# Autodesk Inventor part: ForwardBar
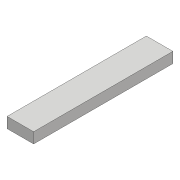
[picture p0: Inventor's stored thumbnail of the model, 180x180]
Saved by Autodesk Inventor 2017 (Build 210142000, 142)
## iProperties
Part Number: ForwardBar
Material: 一般
Document SubType Name: Modeling
Designer: kyushu-hep
Density: 1 g/cm^3
Appearance: 既定
Author: kyushu-hep
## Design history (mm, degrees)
sketch "スケッチ1"
  geometry: L1 (40.301, 16.049)-(-64.699, 16.049); L2 (-64.699, 16.049)-(-64.699, 8.049); L3 (-64.699, 8.049)-(40.301, 8.049); L4 (40.301, 8.049)-(40.301, 16.049); 2 further points
  constraints: 8 end point, 2 parallel, 1 horizontal, 1 perpendicular
  dimensions: "d0" = 105 distance of L3.end L2.end; "d1" = 8 distance of L1.end L2.end
extrude "押し出し1" new body sketch "スケッチ1" distance "d2" = 20; taper "d3" = 0 deg
node "ソリッド1"
